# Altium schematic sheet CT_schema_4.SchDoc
size 313 x 185 mm
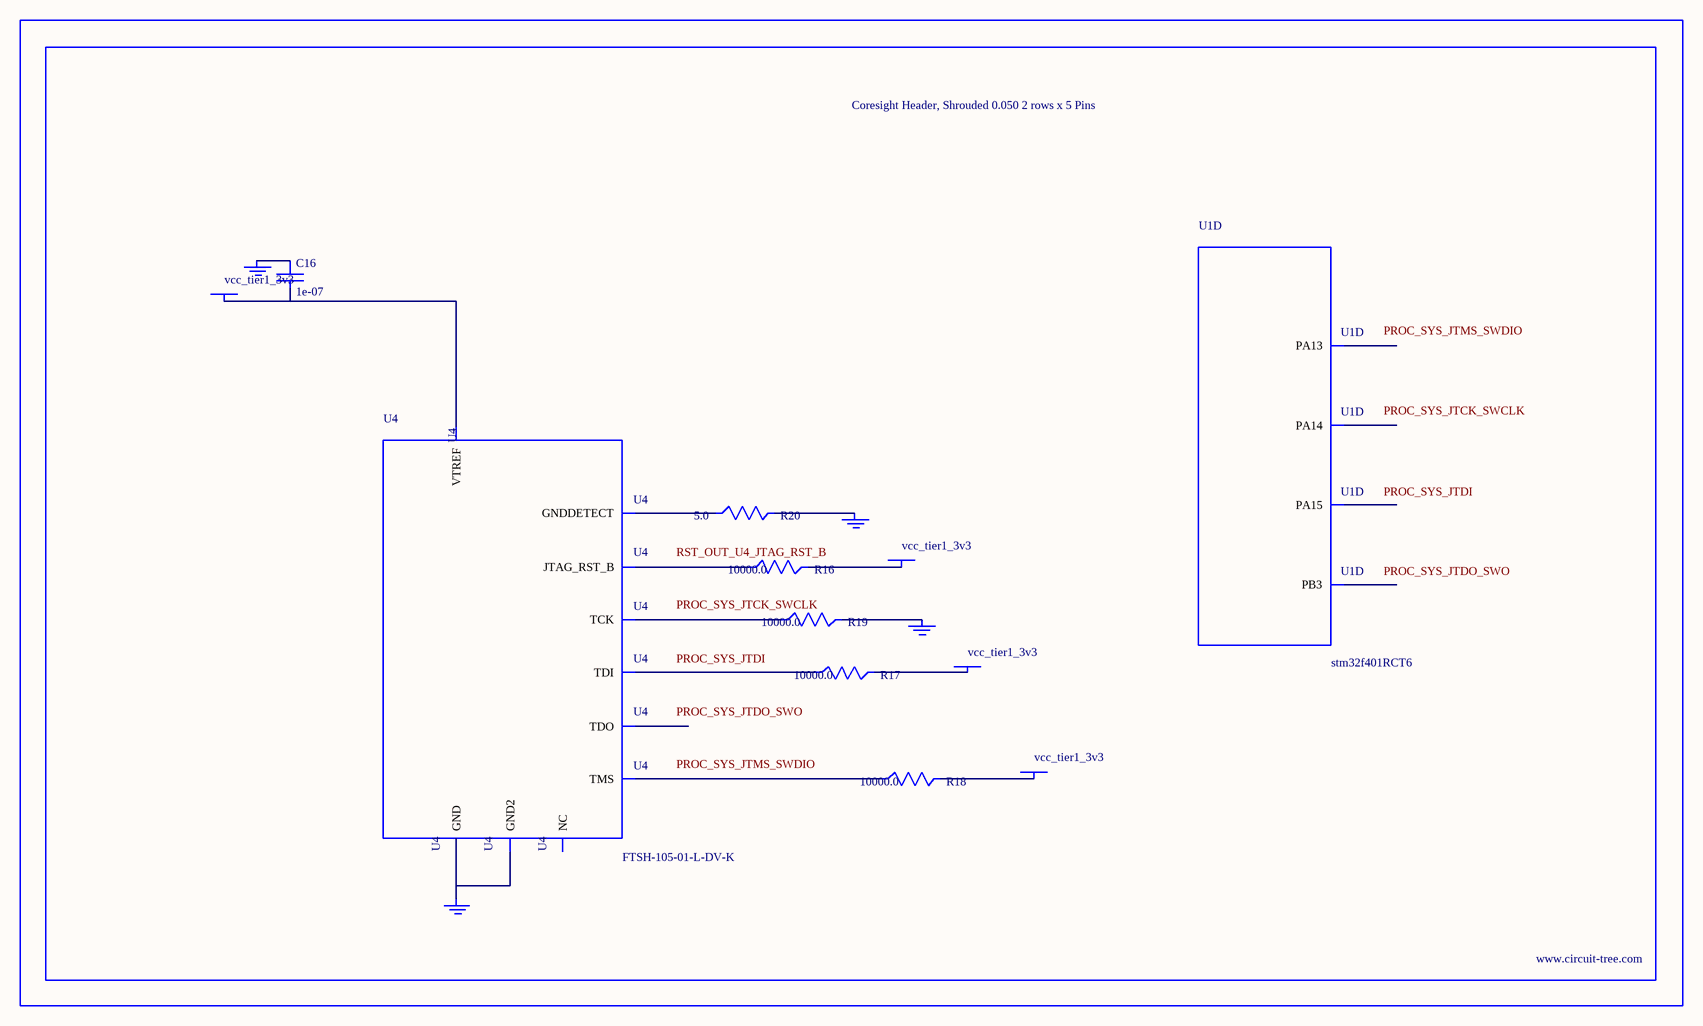
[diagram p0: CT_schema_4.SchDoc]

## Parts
BORDER3  (no value)
C16  1e-07  [C0402]
GND_INSTANCE_3_0  (no value)
GND_INSTANCE_3_1  (no value)
GND_INSTANCE_3_2  (no value)
GND_INSTANCE_3_3  (no value)
POWER_INSTANCE_3_0  vcc_tier1_3v3
POWER_INSTANCE_3_1  vcc_tier1_3v3
POWER_INSTANCE_3_2  vcc_tier1_3v3
POWER_INSTANCE_3_3  vcc_tier1_3v3
R16  10000.0  [R0603]
R17  10000.0  [R0603]
R18  10000.0  [R0603]
R19  10000.0  [R0603]
R20  5.0  [R0603]
U1  stm32f401RCT6  [LQFP64]  (part D of 9)
U4  FTSH-105-01-L-DV-K  [SAMTEC_FTSH-105-01-L-DV-K]

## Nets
NetC16_1: C16.1 GND_INSTANCE_3_0.0(GND)
NetC16_2: C16.2 POWER_INSTANCE_3_0.0(PWR) U4.1(VTREF)
NetGND_INSTANCE_3_1_0: GND_INSTANCE_3_1.0(GND) R19.2
NetGND_INSTANCE_3_2_0: GND_INSTANCE_3_2.0(GND) R20.2
NetGND_INSTANCE_3_3_0: GND_INSTANCE_3_3.0(GND) U4.3(GND) U4.5(GND2)
NetPOWER_INSTANCE_3_1_0: POWER_INSTANCE_3_1.0(PWR) R18.2
NetPOWER_INSTANCE_3_2_0: POWER_INSTANCE_3_2.0(PWR) R17.2
NetPOWER_INSTANCE_3_3_0: POWER_INSTANCE_3_3.0(PWR) R16.2
NetR16_1: R16.1 U4.10(JTAG_RST_B)
NetR17_1: R17.1 U4.8(TDI)
NetR18_1: R18.1 U4.2(TMS)
NetR19_1: R19.1 U4.4(TCK)
NetR20_1: R20.1 U4.9(GNDDETECT)

Not connected (* = marked no-connect by the designer): U1 46(PA13) 49(PA14) 50(PA15) 55(PB3); U4 6(TDO) 7(NC)

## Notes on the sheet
- Labels drawn without touching a wire or pin: PROC_SYS_JTCK_SWCLK, PROC_SYS_JTDI, PROC_SYS_JTDO_SWO, PROC_SYS_JTMS_SWDIO, RST_OUT_U4_JTAG_RST_B

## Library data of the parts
BORDER3 = BORDER_PAGE3
C16 = C0402C104K3RACTU
GND_INSTANCE_3_0-GND_INSTANCE_3_3 = GND
POWER_INSTANCE_3_0-POWER_INSTANCE_3_3 = PWR
R16-R19 = RC0603JR-0710KL
R20 = ERJ-3GEYJ5R1V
